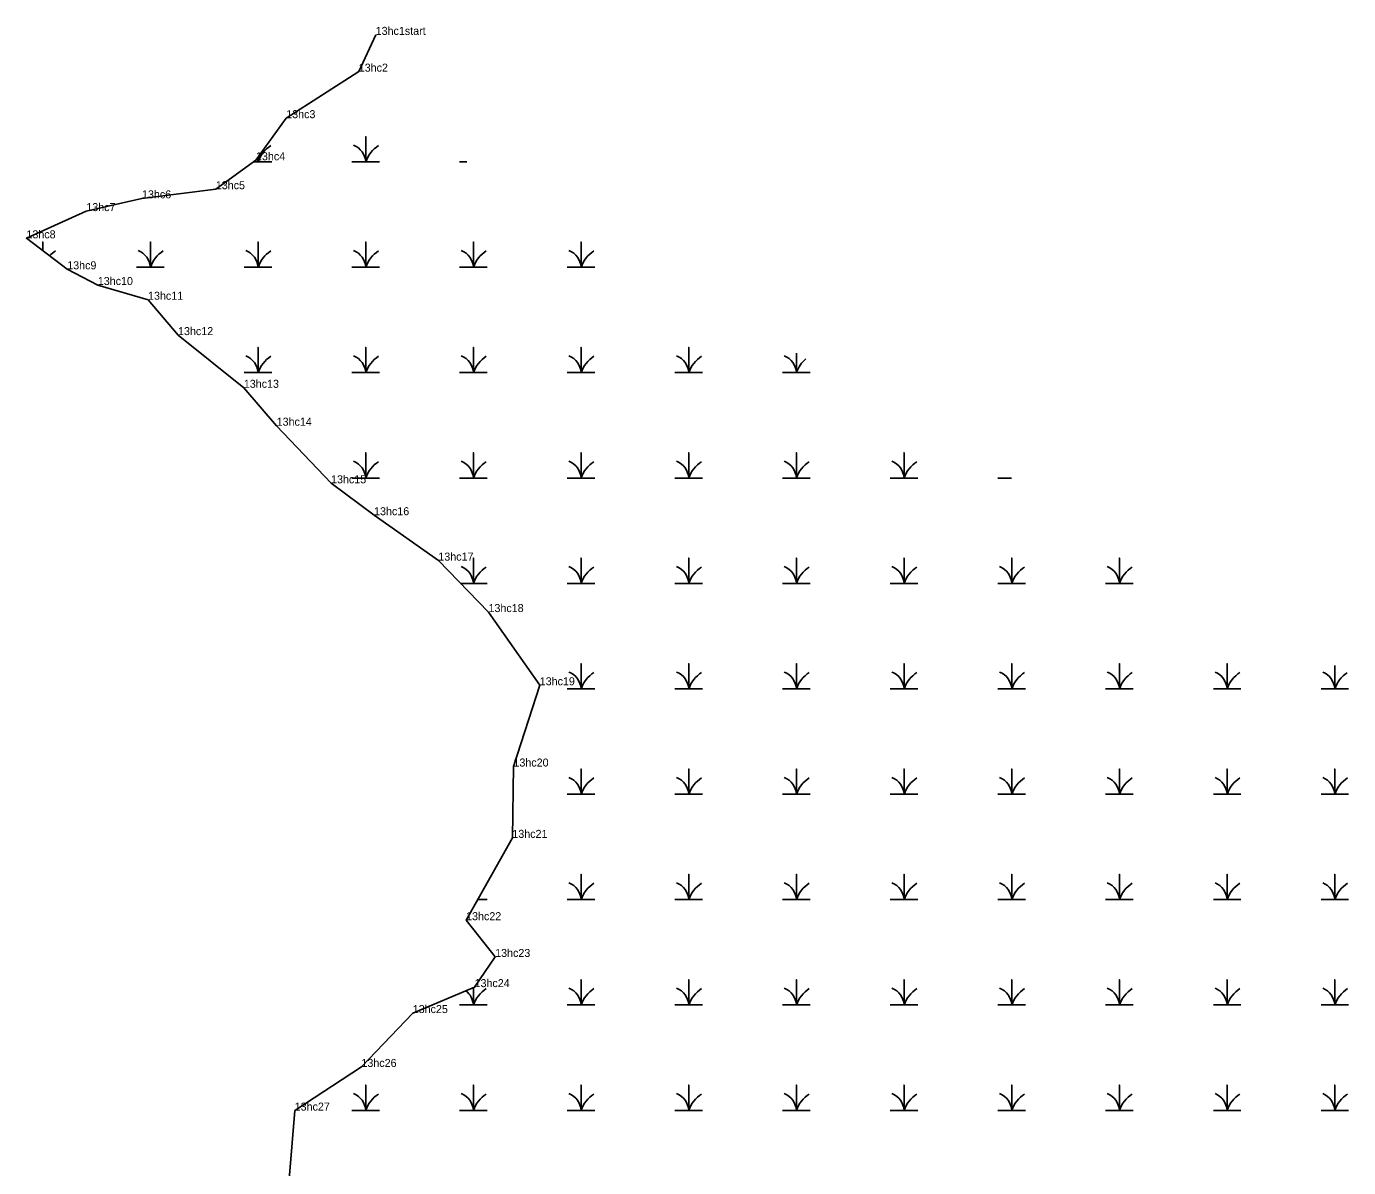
# Model space of a CAD drawing. Extents: x 2072529 to 2268796, y 436423 to 470397.
# Drawn here: x 2247880 to 2248706, y 446696 to 447409 of the extents above; entities that cross this region are included whole.
import ezdxf

# ---------------------------------------------------------------- set-up
doc = ezdxf.new("R2010")
doc.units = 0
for name, color, linetype in [('Exist Environmental Wetland Boundary', 7, 'Continuous'), ('Exist Environmental Wetland Boundary Cogo Comment', 7, 'Continuous'), ('Exist Environmental Wetland Boundary Cogo Point CELL', 7, 'Continuous'), ('Exist Hydro Swamp or Marsh', 7, 'Continuous')]:
    doc.layers.add(name, color=color, linetype=linetype)

msp = doc.modelspace()

# ---------------------------------------------------------------- linework, layer by layer
at = {"layer": 'Exist Environmental Wetland Boundary'}
msp.add_lwpolyline([(2248098.58, 447403.66), (2248088.01, 447380.71), (2248042.72, 447351.65), (2248023.83, 447325.37), (2247998.74, 447307.3), (2247952.63, 447301.6), (2247917.85, 447293.63), (2247880.46, 447276.64), (2247905.92, 447257.29), (2247925.04, 447247.49), (2247956.41, 447238.3), (2247975.16, 447216.21), (2248016.24, 447183.32), (2248036.74, 447159.64), (2248070.73, 447123.69), (2248097.59, 447103.76), (2248137.72, 447075.41), (2248169.06, 447043.29), (2248201.04, 446997.59), (2248184.64, 446946.85), (2248183.95, 446902.32), (2248155.07, 446850.91), (2248173.21, 446827.97), (2248160.36, 446809.13), (2248121.73, 446792.93), (2248089.68, 446759.3), (2248048, 446732.03), (2248043.12, 446671.61)], dxfattribs=at)
at = {"layer": 'Exist Environmental Wetland Boundary Cogo Point CELL'}
for p, q in [((2248098.58, 447403.66), (2248098.58, 447403.66)), ((2248088.01, 447380.71), (2248088.01, 447380.71)), ((2248042.72, 447351.65), (2248042.72, 447351.65)), ((2248023.83, 447325.37), (2248023.83, 447325.37)), ((2247998.74, 447307.3), (2247998.74, 447307.3)), ((2247952.63, 447301.6), (2247952.63, 447301.6)), ((2247917.85, 447293.63), (2247917.85, 447293.63)), ((2247880.46, 447276.64), (2247880.46, 447276.64)), ((2247905.92, 447257.29), (2247905.92, 447257.29)), ((2247925.04, 447247.49), (2247925.04, 447247.49)), ((2247956.41, 447238.3), (2247956.41, 447238.3)), ((2247975.16, 447216.21), (2247975.16, 447216.21)), ((2248016.24, 447183.32), (2248016.24, 447183.32)), ((2248036.74, 447159.64), (2248036.74, 447159.64)), ((2248070.73, 447123.69), (2248070.73, 447123.69)), ((2248097.59, 447103.76), (2248097.59, 447103.76)), ((2248137.72, 447075.41), (2248137.72, 447075.41)), ((2248169.06, 447043.29), (2248169.06, 447043.29)), ((2248201.04, 446997.59), (2248201.04, 446997.59)), ((2248184.64, 446946.85), (2248184.64, 446946.85)), ((2248183.95, 446902.32), (2248183.95, 446902.32)), ((2248155.07, 446850.91), (2248155.07, 446850.91)), ((2248173.21, 446827.97), (2248173.21, 446827.97)), ((2248160.36, 446809.13), (2248160.36, 446809.13)), ((2248121.73, 446792.93), (2248121.73, 446792.93)), ((2248089.68, 446759.3), (2248089.68, 446759.3)), ((2248048, 446732.03), (2248048, 446732.03))]:
    msp.add_line(p, q, dxfattribs=at)
at = {"layer": 'Exist Hydro Swamp or Marsh'}
for points in [[(2248083.76, 447324.37), (2248092.36, 447324.37), (2248092.36, 447340.15), (2248092.36, 447324.37), (2248100.97, 447324.37)], [(2248022.44, 447324.37), (2248025.11, 447324.37), (2248025.11, 447327.15)], [(2248025.11, 447327.15), (2248025.11, 447324.37), (2248033.72, 447324.37)], [(2248151.01, 447324.37), (2248155.46, 447324.37)], [(2247890.61, 447268.92), (2247890.61, 447274.35), (2247890.61, 447268.92)], [(2247949.26, 447258.57), (2247957.86, 447258.57), (2247957.86, 447274.35), (2247957.86, 447258.57), (2247966.47, 447258.57)], [(2248016.51, 447258.57), (2248025.11, 447258.57), (2248025.11, 447274.35), (2248025.11, 447258.57), (2248033.72, 447258.57)], [(2248083.76, 447258.57), (2248092.36, 447258.57), (2248092.36, 447274.35), (2248092.36, 447258.57), (2248100.97, 447258.57)], [(2248151.01, 447258.57), (2248159.61, 447258.57), (2248159.61, 447274.35), (2248159.61, 447258.57), (2248168.22, 447258.57)], [(2248218.26, 447258.57), (2248226.86, 447258.57), (2248226.86, 447274.35), (2248226.86, 447258.57), (2248235.47, 447258.57)], [(2248016.51, 447192.77), (2248025.11, 447192.77), (2248025.11, 447208.55), (2248025.11, 447192.77), (2248033.72, 447192.77)], [(2248083.76, 447192.77), (2248092.36, 447192.77), (2248092.36, 447208.55), (2248092.36, 447192.77), (2248100.97, 447192.77)], [(2248151.01, 447192.77), (2248159.61, 447192.77), (2248159.61, 447208.55), (2248159.61, 447192.77), (2248168.22, 447192.77)], [(2248218.26, 447192.77), (2248226.86, 447192.77), (2248226.86, 447208.55), (2248226.86, 447192.77), (2248235.47, 447192.77)], [(2248285.51, 447192.77), (2248294.11, 447192.77), (2248294.11, 447208.55), (2248294.11, 447192.77), (2248302.72, 447192.77)], [(2248352.76, 447192.77), (2248361.36, 447192.77), (2248361.36, 447204.93)], [(2248361.36, 447204.93), (2248361.36, 447192.77), (2248369.97, 447192.77)], [(2248083.76, 447126.97), (2248092.36, 447126.97), (2248092.36, 447142.75), (2248092.36, 447126.97), (2248100.97, 447126.97)], [(2248151.01, 447126.97), (2248159.61, 447126.97), (2248159.61, 447142.75), (2248159.61, 447126.97), (2248168.22, 447126.97)], [(2248218.26, 447126.97), (2248226.86, 447126.97), (2248226.86, 447142.75), (2248226.86, 447126.97), (2248235.47, 447126.97)], [(2248285.51, 447126.97), (2248294.11, 447126.97), (2248294.11, 447142.75), (2248294.11, 447126.97), (2248302.72, 447126.97)], [(2248352.76, 447126.97), (2248361.36, 447126.97), (2248361.36, 447142.75), (2248361.36, 447126.97), (2248369.97, 447126.97)], [(2248420.01, 447126.97), (2248428.61, 447126.97), (2248428.61, 447142.75), (2248428.61, 447126.97), (2248437.22, 447126.97)], [(2248487.26, 447126.97), (2248495.79, 447126.97)], [(2248151.62, 447061.17), (2248159.61, 447061.17), (2248159.61, 447076.95), (2248159.61, 447061.17), (2248168.22, 447061.17)], [(2248218.26, 447061.17), (2248226.86, 447061.17), (2248226.86, 447076.95), (2248226.86, 447061.17), (2248235.47, 447061.17)], [(2248285.51, 447061.17), (2248294.11, 447061.17), (2248294.11, 447076.95), (2248294.11, 447061.17), (2248302.72, 447061.17)], [(2248352.76, 447061.17), (2248361.36, 447061.17), (2248361.36, 447076.95), (2248361.36, 447061.17), (2248369.97, 447061.17)], [(2248420.01, 447061.17), (2248428.61, 447061.17), (2248428.61, 447076.95), (2248428.61, 447061.17), (2248437.22, 447061.17)], [(2248487.26, 447061.17), (2248495.86, 447061.17), (2248495.86, 447076.95), (2248495.86, 447061.17), (2248504.47, 447061.17)], [(2248554.51, 447061.17), (2248563.11, 447061.17), (2248563.11, 447076.95), (2248563.11, 447061.17), (2248571.72, 447061.17)], [(2248218.26, 446995.37), (2248226.86, 446995.37), (2248226.86, 447011.15), (2248226.86, 446995.37), (2248235.47, 446995.37)], [(2248285.51, 446995.37), (2248294.11, 446995.37), (2248294.11, 447011.15), (2248294.11, 446995.37), (2248302.72, 446995.37)], [(2248352.76, 446995.37), (2248361.36, 446995.37), (2248361.36, 447011.15), (2248361.36, 446995.37), (2248369.97, 446995.37)], [(2248420.01, 446995.37), (2248428.61, 446995.37), (2248428.61, 447011.15), (2248428.61, 446995.37), (2248437.22, 446995.37)], [(2248487.26, 446995.37), (2248495.86, 446995.37), (2248495.86, 447011.15), (2248495.86, 446995.37), (2248504.47, 446995.37)], [(2248554.51, 446995.37), (2248563.11, 446995.37), (2248563.11, 447011.15), (2248563.11, 446995.37), (2248571.72, 446995.37)], [(2248621.76, 446995.37), (2248630.36, 446995.37), (2248630.36, 447011.15), (2248630.36, 446995.37), (2248638.97, 446995.37)], [(2248689.01, 446995.37), (2248697.61, 446995.37), (2248697.61, 447009.9)], [(2248697.61, 447009.9), (2248697.61, 446995.37), (2248706.22, 446995.37)], [(2248218.26, 446929.57), (2248226.86, 446929.57), (2248226.86, 446945.35), (2248226.86, 446929.57), (2248235.47, 446929.57)], [(2248285.51, 446929.57), (2248294.11, 446929.57), (2248294.11, 446945.35), (2248294.11, 446929.57), (2248302.72, 446929.57)], [(2248352.76, 446929.57), (2248361.36, 446929.57), (2248361.36, 446945.35), (2248361.36, 446929.57), (2248369.97, 446929.57)], [(2248420.01, 446929.57), (2248428.61, 446929.57), (2248428.61, 446945.35), (2248428.61, 446929.57), (2248437.22, 446929.57)], [(2248487.26, 446929.57), (2248495.86, 446929.57), (2248495.86, 446945.35), (2248495.86, 446929.57), (2248504.47, 446929.57)], [(2248554.51, 446929.57), (2248563.11, 446929.57), (2248563.11, 446945.35), (2248563.11, 446929.57), (2248571.72, 446929.57)], [(2248621.76, 446929.57), (2248630.36, 446929.57), (2248630.36, 446945.35), (2248630.36, 446929.57), (2248638.97, 446929.57)], [(2248689.01, 446929.57), (2248697.61, 446929.57), (2248697.61, 446945.35), (2248697.61, 446929.57), (2248706.22, 446929.57)], [(2248218.26, 446863.77), (2248226.86, 446863.77), (2248226.86, 446879.55), (2248226.86, 446863.77), (2248235.47, 446863.77)], [(2248285.51, 446863.77), (2248294.11, 446863.77), (2248294.11, 446879.55), (2248294.11, 446863.77), (2248302.72, 446863.77)], [(2248352.76, 446863.77), (2248361.36, 446863.77), (2248361.36, 446879.55), (2248361.36, 446863.77), (2248369.97, 446863.77)], [(2248420.01, 446863.77), (2248428.61, 446863.77), (2248428.61, 446879.55), (2248428.61, 446863.77), (2248437.22, 446863.77)], [(2248487.26, 446863.77), (2248495.86, 446863.77), (2248495.86, 446879.55), (2248495.86, 446863.77), (2248504.47, 446863.77)], [(2248554.51, 446863.77), (2248563.11, 446863.77), (2248563.11, 446879.55), (2248563.11, 446863.77), (2248571.72, 446863.77)], [(2248621.76, 446863.77), (2248630.36, 446863.77), (2248630.36, 446879.55), (2248630.36, 446863.77), (2248638.97, 446863.77)], [(2248689.01, 446863.77), (2248697.61, 446863.77), (2248697.61, 446879.55), (2248697.61, 446863.77), (2248706.22, 446863.77)], [(2248162.29, 446863.77), (2248168.22, 446863.77)], [(2248218.26, 446797.97), (2248226.86, 446797.97), (2248226.86, 446813.75), (2248226.86, 446797.97), (2248235.47, 446797.97)], [(2248285.51, 446797.97), (2248294.11, 446797.97), (2248294.11, 446813.75), (2248294.11, 446797.97), (2248302.72, 446797.97)], [(2248352.76, 446797.97), (2248361.36, 446797.97), (2248361.36, 446813.75), (2248361.36, 446797.97), (2248369.97, 446797.97)], [(2248420.01, 446797.97), (2248428.61, 446797.97), (2248428.61, 446813.75), (2248428.61, 446797.97), (2248437.22, 446797.97)], [(2248487.26, 446797.97), (2248495.86, 446797.97), (2248495.86, 446813.75), (2248495.86, 446797.97), (2248504.47, 446797.97)], [(2248554.51, 446797.97), (2248563.11, 446797.97), (2248563.11, 446813.75), (2248563.11, 446797.97), (2248571.72, 446797.97)], [(2248621.76, 446797.97), (2248630.36, 446797.97), (2248630.36, 446813.75), (2248630.36, 446797.97), (2248638.97, 446797.97)], [(2248689.01, 446797.97), (2248697.61, 446797.97), (2248697.61, 446813.75), (2248697.61, 446797.97), (2248706.22, 446797.97)], [(2248151.01, 446797.97), (2248159.61, 446797.97), (2248159.61, 446808.82)], [(2248159.61, 446808.82), (2248159.61, 446797.97), (2248168.22, 446797.97)], [(2248083.76, 446732.17), (2248092.36, 446732.17), (2248092.36, 446747.95), (2248092.36, 446732.17), (2248100.97, 446732.17)], [(2248151.01, 446732.17), (2248159.61, 446732.17), (2248159.61, 446747.95), (2248159.61, 446732.17), (2248168.22, 446732.17)], [(2248218.26, 446732.17), (2248226.86, 446732.17), (2248226.86, 446747.95), (2248226.86, 446732.17), (2248235.47, 446732.17)], [(2248285.51, 446732.17), (2248294.11, 446732.17), (2248294.11, 446747.95), (2248294.11, 446732.17), (2248302.72, 446732.17)], [(2248352.76, 446732.17), (2248361.36, 446732.17), (2248361.36, 446747.95), (2248361.36, 446732.17), (2248369.97, 446732.17)], [(2248420.01, 446732.17), (2248428.61, 446732.17), (2248428.61, 446747.95), (2248428.61, 446732.17), (2248437.22, 446732.17)], [(2248487.26, 446732.17), (2248495.86, 446732.17), (2248495.86, 446747.95), (2248495.86, 446732.17), (2248504.47, 446732.17)], [(2248554.51, 446732.17), (2248563.11, 446732.17), (2248563.11, 446747.95), (2248563.11, 446732.17), (2248571.72, 446732.17)], [(2248621.76, 446732.17), (2248630.36, 446732.17), (2248630.36, 446747.95), (2248630.36, 446732.17), (2248638.97, 446732.17)], [(2248689.01, 446732.17), (2248697.61, 446732.17), (2248697.61, 446747.95), (2248697.61, 446732.17), (2248706.22, 446732.17)]]:
    msp.add_lwpolyline(points, dxfattribs=at)
for centre, radius, start, end in [((2248043.36, 447318.3), 19.22, 122.12745, 161.62219), ((2248080.1, 447323.48), 12.3, 4.14034, 67.53497), ((2248110.61, 447318.3), 19.22, 122.12745, 161.62219), ((2248012.85, 447323.48), 12.3, 4.14034, 14.8358), ((2247908.86, 447252.5), 19.22, 122.12745, 136.6945), ((2247945.6, 447257.68), 12.3, 4.14034, 67.53497), ((2247976.11, 447252.5), 19.22, 122.12745, 161.62219), ((2248012.85, 447257.68), 12.3, 4.14034, 67.53497), ((2248043.36, 447252.5), 19.22, 122.12745, 161.62219), ((2248080.1, 447257.68), 12.3, 4.14034, 67.53497), ((2248110.61, 447252.5), 19.22, 122.12745, 161.62219), ((2248147.35, 447257.68), 12.3, 4.14034, 67.53497), ((2248177.86, 447252.5), 19.22, 122.12745, 161.62219), ((2248214.6, 447257.68), 12.3, 4.14034, 67.53497), ((2248245.11, 447252.5), 19.22, 122.12745, 161.62219), ((2248012.85, 447191.88), 12.3, 4.14034, 67.53497), ((2248043.36, 447186.7), 19.22, 122.12745, 161.62219), ((2248080.1, 447191.88), 12.3, 4.14034, 67.53497), ((2248110.61, 447186.7), 19.22, 122.12745, 161.62219), ((2248147.35, 447191.88), 12.3, 4.14034, 67.53497), ((2248177.86, 447186.7), 19.22, 122.12745, 161.62219), ((2248214.6, 447191.88), 12.3, 4.14034, 67.53497), ((2248245.11, 447186.7), 19.22, 122.12745, 161.62219), ((2248281.85, 447191.88), 12.3, 4.14034, 67.53497), ((2248312.36, 447186.7), 19.22, 122.12745, 161.62219), ((2248349.1, 447191.88), 12.3, 4.14034, 67.53497), ((2248379.61, 447186.7), 19.22, 129.75565, 161.62219), ((2248080.1, 447126.08), 12.3, 4.14034, 67.53497), ((2248110.61, 447120.9), 19.22, 122.12745, 161.62219), ((2248147.35, 447126.08), 12.3, 4.14034, 67.53497), ((2248177.86, 447120.9), 19.22, 122.12745, 161.62219), ((2248214.6, 447126.08), 12.3, 4.14034, 67.53497), ((2248245.11, 447120.9), 19.22, 122.12745, 161.62219), ((2248281.85, 447126.08), 12.3, 4.14034, 67.53497), ((2248312.36, 447120.9), 19.22, 122.12745, 161.62219), ((2248349.1, 447126.08), 12.3, 4.14034, 67.53497), ((2248379.61, 447120.9), 19.22, 122.12745, 161.62219), ((2248416.35, 447126.08), 12.3, 4.14034, 67.53497), ((2248446.86, 447120.9), 19.22, 122.12745, 161.62219), ((2248147.35, 447060.28), 12.3, 4.14034, 67.53497), ((2248177.86, 447055.1), 19.22, 122.12745, 161.62219), ((2248214.6, 447060.28), 12.3, 4.14034, 67.53497), ((2248245.11, 447055.1), 19.22, 122.12745, 161.62219), ((2248281.85, 447060.28), 12.3, 4.14034, 67.53497), ((2248312.36, 447055.1), 19.22, 122.12745, 161.62219), ((2248349.1, 447060.28), 12.3, 4.14034, 67.53497), ((2248379.61, 447055.1), 19.22, 122.12745, 161.62219), ((2248416.35, 447060.28), 12.3, 4.14034, 67.53497), ((2248446.86, 447055.1), 19.22, 122.12745, 161.62219), ((2248483.6, 447060.28), 12.3, 4.14034, 67.53497), ((2248514.11, 447055.1), 19.22, 122.12745, 161.62219), ((2248550.85, 447060.28), 12.3, 4.14034, 67.53497), ((2248581.36, 447055.1), 19.22, 122.12745, 161.62219), ((2248214.6, 446994.48), 12.3, 4.14034, 67.53497), ((2248245.11, 446989.3), 19.22, 122.12745, 161.62219), ((2248281.85, 446994.48), 12.3, 4.14034, 67.53497), ((2248312.36, 446989.3), 19.22, 122.12745, 161.62219), ((2248349.1, 446994.48), 12.3, 4.14034, 67.53497), ((2248379.61, 446989.3), 19.22, 122.12745, 161.62219), ((2248416.35, 446994.48), 12.3, 4.14034, 67.53497), ((2248446.86, 446989.3), 19.22, 122.12745, 161.62219), ((2248483.6, 446994.48), 12.3, 4.14034, 67.53497), ((2248514.11, 446989.3), 19.22, 122.12745, 161.62219), ((2248550.85, 446994.48), 12.3, 4.14034, 67.53497), ((2248581.36, 446989.3), 19.22, 122.12745, 161.62219), ((2248618.1, 446994.48), 12.3, 4.14034, 67.53497), ((2248648.61, 446989.3), 19.22, 122.12745, 161.62219), ((2248685.35, 446994.48), 12.3, 4.14034, 67.53497), ((2248715.86, 446989.3), 19.22, 123.1007, 161.62219), ((2248214.6, 446928.68), 12.3, 4.14034, 67.53497), ((2248245.11, 446923.5), 19.22, 122.12745, 161.62219), ((2248281.85, 446928.68), 12.3, 4.14034, 67.53497), ((2248312.36, 446923.5), 19.22, 122.12745, 161.62219), ((2248349.1, 446928.68), 12.3, 4.14034, 67.53497), ((2248379.61, 446923.5), 19.22, 122.12745, 161.62219), ((2248416.35, 446928.68), 12.3, 4.14034, 67.53497), ((2248446.86, 446923.5), 19.22, 122.12745, 161.62219), ((2248483.6, 446928.68), 12.3, 4.14034, 67.53497), ((2248514.11, 446923.5), 19.22, 122.12745, 161.62219), ((2248550.85, 446928.68), 12.3, 4.14034, 67.53497), ((2248581.36, 446923.5), 19.22, 122.12745, 161.62219), ((2248618.1, 446928.68), 12.3, 4.14034, 67.53497), ((2248648.61, 446923.5), 19.22, 122.12745, 161.62219), ((2248685.35, 446928.68), 12.3, 4.14034, 67.53497), ((2248715.86, 446923.5), 19.22, 122.12745, 161.62219), ((2248214.6, 446862.88), 12.3, 4.14034, 67.53497), ((2248245.11, 446857.7), 19.22, 122.12745, 161.62219), ((2248281.85, 446862.88), 12.3, 4.14034, 67.53497), ((2248312.36, 446857.7), 19.22, 122.12745, 161.62219), ((2248349.1, 446862.88), 12.3, 4.14034, 67.53497), ((2248379.61, 446857.7), 19.22, 122.12745, 161.62219), ((2248416.35, 446862.88), 12.3, 4.14034, 67.53497), ((2248446.86, 446857.7), 19.22, 122.12745, 161.62219), ((2248483.6, 446862.88), 12.3, 4.14034, 67.53497), ((2248514.11, 446857.7), 19.22, 122.12745, 161.62219), ((2248550.85, 446862.88), 12.3, 4.14034, 67.53497), ((2248581.36, 446857.7), 19.22, 122.12745, 161.62219), ((2248618.1, 446862.88), 12.3, 4.14034, 67.53497), ((2248648.61, 446857.7), 19.22, 122.12745, 161.62219), ((2248685.35, 446862.88), 12.3, 4.14034, 67.53497), ((2248715.86, 446857.7), 19.22, 122.12745, 161.62219), ((2248147.35, 446797.08), 12.3, 4.14034, 52.39277), ((2248177.86, 446791.9), 19.22, 122.12745, 161.62219), ((2248214.6, 446797.08), 12.3, 4.14034, 67.53497), ((2248245.11, 446791.9), 19.22, 122.12745, 161.62219), ((2248281.85, 446797.08), 12.3, 4.14034, 67.53497), ((2248312.36, 446791.9), 19.22, 122.12745, 161.62219), ((2248349.1, 446797.08), 12.3, 4.14034, 67.53497), ((2248379.61, 446791.9), 19.22, 122.12745, 161.62219), ((2248416.35, 446797.08), 12.3, 4.14034, 67.53497), ((2248446.86, 446791.9), 19.22, 122.12745, 161.62219), ((2248483.6, 446797.08), 12.3, 4.14034, 67.53497), ((2248514.11, 446791.9), 19.22, 122.12745, 161.62219), ((2248550.85, 446797.08), 12.3, 4.14034, 67.53497), ((2248581.36, 446791.9), 19.22, 122.12745, 161.62219), ((2248618.1, 446797.08), 12.3, 4.14034, 67.53497), ((2248648.61, 446791.9), 19.22, 122.12745, 161.62219), ((2248685.35, 446797.08), 12.3, 4.14034, 67.53497), ((2248715.86, 446791.9), 19.22, 122.12745, 161.62219), ((2248080.1, 446731.28), 12.3, 4.14034, 67.53497), ((2248110.61, 446726.1), 19.22, 122.12745, 161.62219), ((2248147.35, 446731.28), 12.3, 4.14034, 67.53497), ((2248177.86, 446726.1), 19.22, 122.12745, 161.62219), ((2248214.6, 446731.28), 12.3, 4.14034, 67.53497), ((2248245.11, 446726.1), 19.22, 122.12745, 161.62219), ((2248281.85, 446731.28), 12.3, 4.14034, 67.53497), ((2248312.36, 446726.1), 19.22, 122.12745, 161.62219), ((2248349.1, 446731.28), 12.3, 4.14034, 67.53497), ((2248379.61, 446726.1), 19.22, 122.12745, 161.62219), ((2248416.35, 446731.28), 12.3, 4.14034, 67.53497), ((2248446.86, 446726.1), 19.22, 122.12745, 161.62219), ((2248483.6, 446731.28), 12.3, 4.14034, 67.53497), ((2248514.11, 446726.1), 19.22, 122.12745, 161.62219), ((2248550.85, 446731.28), 12.3, 4.14034, 67.53497), ((2248581.36, 446726.1), 19.22, 122.12745, 161.62219), ((2248618.1, 446731.28), 12.3, 4.14034, 67.53497), ((2248648.61, 446726.1), 19.22, 122.12745, 161.62219), ((2248685.35, 446731.28), 12.3, 4.14034, 67.53497), ((2248715.86, 446726.1), 19.22, 122.12745, 161.62219)]:
    msp.add_arc(centre, radius, start, end, dxfattribs=at)

# ---------------------------------------------------------------- texts
at = {"layer": 'Exist Environmental Wetland Boundary Cogo Comment'}
for s, p in [('13hc1start', (2248098.58, 447403.66)), ('13hc2', (2248088.01, 447380.71)), ('13hc3', (2248042.72, 447351.65)), ('13hc4', (2248023.83, 447325.37)), ('13hc6', (2247952.63, 447301.6)), ('13hc5', (2247998.74, 447307.3)), ('13hc7', (2247917.85, 447293.63)), ('13hc8', (2247880.46, 447276.64)), ('13hc9', (2247905.92, 447257.29)), ('13hc10', (2247925.04, 447247.49)), ('13hc11', (2247956.41, 447238.3)), ('13hc12', (2247975.16, 447216.21)), ('13hc13', (2248016.24, 447183.32)), ('13hc14', (2248036.74, 447159.64)), ('13hc15', (2248070.73, 447123.69)), ('13hc16', (2248097.59, 447103.76)), ('13hc17', (2248137.72, 447075.41)), ('13hc18', (2248169.06, 447043.29)), ('13hc19', (2248201.04, 446997.59)), ('13hc20', (2248184.64, 446946.85)), ('13hc21', (2248183.95, 446902.32)), ('13hc22', (2248155.07, 446850.91)), ('13hc23', (2248173.21, 446827.97)), ('13hc24', (2248160.36, 446809.13)), ('13hc25', (2248121.73, 446792.93)), ('13hc26', (2248089.68, 446759.3)), ('13hc27', (2248048, 446732.03))]:
    msp.add_text(s, height=5, dxfattribs=at).set_placement(p)

doc.saveas('drawing.dxf')
